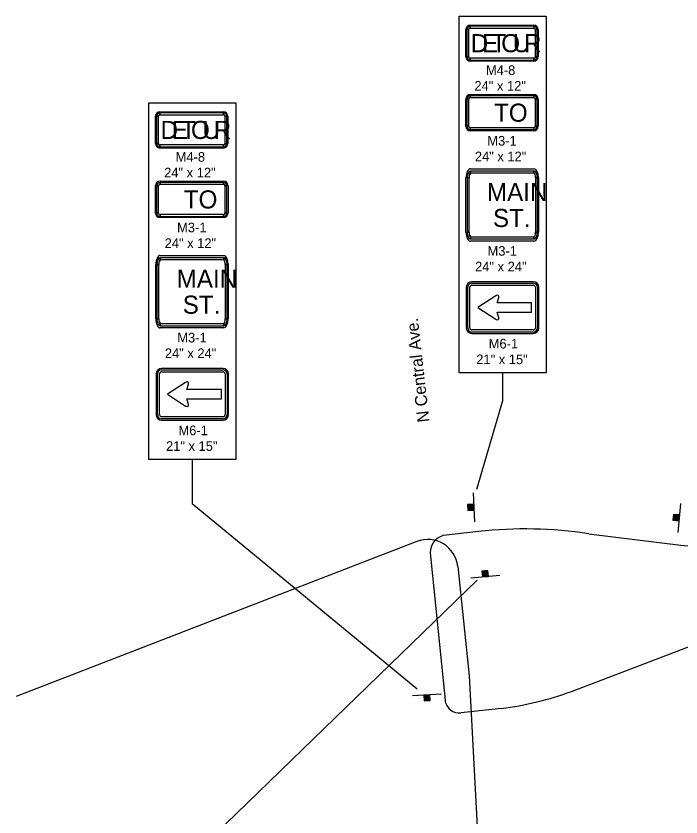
# Model space of a CAD drawing. Extents: x 10133 to 81668, y 6132 to 11018.
# Drawn here: x 10419 to 10970, y 8934 to 9599 of the extents above; entities that cross this region are included whole.
import ezdxf

# ---------------------------------------------------------------- set-up
doc = ezdxf.new("R2010")
doc.units = 0
for name, color, linetype in [('dsnTextFinalPlan', 7, 'Continuous'), ('Level 10', 7, 'Continuous'), ('Level 2', 7, 'Continuous'), ('Level 5', 7, 'Continuous')]:
    doc.layers.add(name, color=color, linetype=linetype)

msp = doc.modelspace()

# ---------------------------------------------------------------- linework, layer by layer
at = {"layer": 'dsnTextFinalPlan'}
for p, q in [((10797.94, 9203.03), (10798.93, 9179.05)), ((10793.69, 9193.37), (10793.89, 9188.49)), ((10794.17, 9188.5), (10793.96, 9193.38)), ((10794.16, 9193.39), (10794.36, 9188.51)), ((10794.64, 9188.52), (10794.44, 9193.4)), ((10794.63, 9193.41), (10794.82, 9188.53)), ((10795.2, 9188.55), (10795.01, 9193.42)), ((10795.19, 9193.43), (10795.39, 9188.56)), ((10795.77, 9188.57), (10795.57, 9193.44)), ((10795.89, 9193.46), (10796.1, 9188.59)), ((10796.37, 9188.6), (10796.19, 9193.47)), ((10796.37, 9193.48), (10796.57, 9188.6)), ((10796.8, 9188.61), (10796.6, 9193.49)), ((10796.89, 9193.5), (10797.09, 9188.63)), ((10797.27, 9188.63), (10797.07, 9193.51)), ((10797.27, 9193.51), (10797.47, 9188.64)), ((10797.7, 9188.65), (10797.5, 9193.52)), ((10797.72, 9193.53), (10797.93, 9188.66)), ((10798.17, 9188.67), (10797.97, 9193.54)), ((10969.88, 9194.1), (10967.69, 9170.2)), ((10964.39, 9185.09), (10963.94, 9180.23)), ((10964.22, 9180.21), (10964.67, 9185.06)), ((10964.86, 9185.05), (10964.42, 9180.19)), ((10964.69, 9180.17), (10965.14, 9185.02)), ((10965.33, 9185), (10964.87, 9180.15)), ((10965.25, 9180.11), (10965.71, 9184.97)), ((10965.89, 9184.95), (10965.44, 9180.1)), ((10965.82, 9180.06), (10966.26, 9184.92)), ((10966.59, 9184.89), (10966.14, 9180.03)), ((10966.42, 9180.01), (10966.88, 9184.86)), ((10967.06, 9184.85), (10966.62, 9179.99)), ((10966.84, 9179.97), (10967.29, 9184.82)), ((10967.58, 9184.8), (10967.14, 9179.94)), ((10967.32, 9179.92), (10967.76, 9184.78)), ((10967.96, 9184.76), (10967.51, 9179.91)), ((10967.74, 9179.89), (10968.19, 9184.74)), ((10968.41, 9184.72), (10967.97, 9179.86)), ((10968.21, 9179.84), (10968.66, 9184.7)), ((10802.29, 9171.01), (10775.92, 9168)), ((10893.98, 9169.13), (10970.3, 9159.56)), ((10751.26, 9162.72), (10418.8, 9034.15)), ((10762.42, 9153.32), (10774.67, 9031.09)), ((10810.12, 9138.18), (10805.26, 9137.77)), ((10805.29, 9137.49), (10810.15, 9137.9)), ((10810.16, 9137.7), (10805.3, 9137.29)), ((10805.33, 9137.02), (10810.19, 9137.43)), ((10810.2, 9137.23), (10805.34, 9136.84)), ((10805.37, 9136.46), (10810.23, 9136.86)), ((10810.25, 9136.68), (10805.39, 9136.27)), ((10805.42, 9135.89), (10810.28, 9136.3)), ((10810.31, 9135.98), (10805.45, 9135.57)), ((10805.47, 9135.29), (10810.33, 9135.68)), ((10810.35, 9135.5), (10805.49, 9135.09)), ((10805.51, 9134.86), (10810.37, 9135.27)), ((10810.39, 9134.98), (10805.53, 9134.57)), ((10805.55, 9134.39), (10810.41, 9134.8)), ((10810.42, 9134.61), (10805.56, 9134.2)), ((10805.58, 9133.97), (10810.44, 9134.38)), ((10819.96, 9134.34), (10796.04, 9132.33)), ((10810.46, 9134.15), (10805.6, 9133.74)), ((10805.62, 9133.5), (10810.48, 9133.9)), ((10879.55, 9038.29), (11002.94, 9085.49)), ((10747.66, 9034.72), (10771.62, 9036.19)), ((10762.01, 9035.24), (10757.14, 9034.94)), ((10757.16, 9034.7), (10762.03, 9034.99)), ((10762.04, 9034.77), (10757.17, 9034.47)), ((10757.19, 9034.24), (10762.06, 9034.54)), ((10762.07, 9034.34), (10757.2, 9034.04)), ((10757.21, 9033.86), (10762.08, 9034.16)), ((10762.1, 9033.87), (10757.23, 9033.57)), ((10757.24, 9033.34), (10762.11, 9033.64)), ((10762.12, 9033.44), (10757.25, 9033.16)), ((10757.27, 9032.87), (10762.14, 9033.17)), ((10762.16, 9032.84), (10757.29, 9032.54)), ((10757.31, 9032.16), (10762.18, 9032.46)), ((10762.19, 9032.27), (10757.33, 9031.99)), ((10757.35, 9031.61), (10762.22, 9031.89)), ((10762.23, 9031.71), (10757.36, 9031.41)), ((10757.38, 9031.14), (10762.25, 9031.43)), ((10762.26, 9031.24), (10757.39, 9030.94)), ((10757.41, 9030.66), (10762.27, 9030.96)), ((10821.28, 9023.98), (10787.9, 9020.36))]:
    msp.add_line(p, q, dxfattribs=at)
for points in [[(10786.31, 9598.82), (10858.38, 9598.82), (10858.38, 9302.72), (10786.31, 9302.72)], [(10786.31, 9598.82), (10858.38, 9598.82), (10858.38, 9302.72), (10786.31, 9302.72)], [(10528.99, 9526.84), (10601.05, 9526.84), (10601.05, 9230.74), (10528.99, 9230.74)], [(10528.99, 9526.84), (10601.05, 9526.84), (10601.05, 9230.74), (10528.99, 9230.74)], [(10798.45, 9188.68), (10798.25, 9193.59), (10793.34, 9193.38), (10793.55, 9188.48)], [(10968.49, 9179.82), (10968.94, 9184.71), (10964.05, 9185.15), (10963.6, 9180.27)], [(10805.65, 9133.22), (10810.54, 9133.63), (10810.13, 9138.52), (10805.23, 9138.11)], [(10761.99, 9035.52), (10757.09, 9035.22), (10757.39, 9030.32), (10762.3, 9030.62)]]:
    msp.add_lwpolyline(points, close=True, dxfattribs=at)
for points in [[(10822.35, 9302.72), (10822.35, 9279.46), (10800.59, 9205.8)], [(10565.02, 9230.74), (10565.02, 9194.13), (10751.41, 9040.3)], [(10785.14, 9142), (10794.64, 9051.15), (10817.78, 8612.5)], [(10556.31, 8842.44), (10556.31, 8892.79), (10801.13, 9130.54)]]:
    msp.add_lwpolyline(points, dxfattribs=at)
for centre, radius, start, end in [((10776.68, 9153.75), 14.27, 93.05001, 181.74125), ((10840.81, 8812.25), 360.82, 81.52677, 96.12941), ((10760.28, 9139.4), 25, 5.96861, 111.14197), ((11056.79, 10017.57), 862.36, 264.24449, 273.255), ((10786, 9293.41), 271.73, 277.46158, 290.13827), ((10786.61, 9032.29), 12, 185.72428, 276.20159)]:
    msp.add_arc(centre, radius, start, end, dxfattribs=at)
at = {"layer": 'Level 10'}
for p, q in [((10791.76, 9565), (10791.76, 9587.55)), ((10792.7, 9587.55), (10794.27, 9587.55)), ((10795.52, 9591.31), (10848.13, 9591.31)), ((10795.52, 9588.8), (10795.52, 9590.37)), ((10848.13, 9590.37), (10848.13, 9588.8)), ((10849.39, 9587.55), (10850.95, 9587.55)), ((10851.89, 9587.55), (10851.89, 9565)), ((10794.27, 9565), (10792.7, 9565)), ((10795.52, 9562.19), (10795.52, 9563.75)), ((10848.13, 9561.25), (10795.52, 9561.25)), ((10848.13, 9563.75), (10848.13, 9562.19)), ((10850.95, 9565), (10849.39, 9565)), ((10795.57, 9533.62), (10848.18, 9533.62)), ((10791.81, 9507.32), (10791.81, 9529.87)), ((10792.75, 9529.87), (10794.31, 9529.87)), ((10795.57, 9531.12), (10795.57, 9532.68)), ((10848.18, 9532.68), (10848.18, 9531.12)), ((10849.43, 9529.87), (10851, 9529.87)), ((10851.94, 9529.87), (10851.94, 9507.32)), ((10534.44, 9493.02), (10534.44, 9515.57)), ((10535.38, 9515.57), (10536.94, 9515.57)), ((10538.2, 9519.33), (10590.81, 9519.33)), ((10538.2, 9516.82), (10538.2, 9518.39)), ((10590.81, 9518.39), (10590.81, 9516.82)), ((10592.06, 9515.57), (10593.63, 9515.57)), ((10594.57, 9515.57), (10594.57, 9493.02)), ((10794.31, 9507.32), (10792.75, 9507.32)), ((10851, 9507.32), (10849.43, 9507.32)), ((10795.57, 9504.5), (10795.57, 9506.06)), ((10848.18, 9503.56), (10795.57, 9503.56)), ((10848.18, 9506.06), (10848.18, 9504.5)), ((10536.94, 9493.02), (10535.38, 9493.02)), ((10538.2, 9490.2), (10538.2, 9491.77)), ((10590.81, 9489.26), (10538.2, 9489.26)), ((10590.81, 9491.77), (10590.81, 9490.2)), ((10593.63, 9493.02), (10592.06, 9493.02)), ((10795.76, 9472.04), (10848.37, 9472.04)), ((10795.76, 9467.03), (10795.76, 9470.16)), ((10848.37, 9470.16), (10848.37, 9468.6)), ((10538.24, 9461.64), (10590.86, 9461.64)), ((10538.24, 9459.14), (10538.24, 9460.7)), ((10590.86, 9460.7), (10590.86, 9459.14)), ((10792, 9419.43), (10792, 9464.52)), ((10792.94, 9464.52), (10794.51, 9464.52)), ((10849.62, 9464.52), (10851.19, 9464.52)), ((10852.13, 9464.52), (10852.13, 9419.43)), ((10534.48, 9435.34), (10534.48, 9457.88)), ((10535.42, 9457.88), (10536.99, 9457.88)), ((10592.11, 9457.88), (10593.67, 9457.88)), ((10594.61, 9457.88), (10594.61, 9435.34)), ((10536.99, 9435.34), (10535.42, 9435.34)), ((10538.24, 9432.52), (10538.24, 9434.08)), ((10590.86, 9434.08), (10590.86, 9432.52)), ((10593.67, 9435.34), (10592.11, 9435.34)), ((10590.86, 9431.58), (10538.24, 9431.58)), ((10794.51, 9419.43), (10792.94, 9419.43)), ((10795.76, 9413.79), (10795.76, 9416.92)), ((10848.37, 9415.36), (10848.37, 9413.79)), ((10851.19, 9419.43), (10849.62, 9419.43)), ((10848.37, 9411.91), (10795.76, 9411.91)), ((10538.43, 9400.06), (10591.05, 9400.06)), ((10538.43, 9395.05), (10538.43, 9398.18)), ((10591.05, 9398.18), (10591.05, 9396.61)), ((10534.68, 9347.45), (10534.68, 9392.54)), ((10535.61, 9392.54), (10537.18, 9392.54)), ((10592.3, 9392.54), (10593.86, 9392.54)), ((10594.8, 9392.54), (10594.8, 9347.45)), ((10792.26, 9373.75), (10792.26, 9339.96)), ((10793.42, 9339.96), (10793.42, 9373.75)), ((10795.14, 9339.96), (10795.14, 9373.75)), ((10847.81, 9378.33), (10796.84, 9378.33)), ((10796.85, 9377.19), (10847.82, 9377.19)), ((10796.85, 9375.47), (10847.82, 9375.47)), ((10849.54, 9373.75), (10849.54, 9339.96)), ((10851.26, 9373.75), (10851.26, 9339.96)), ((10852.39, 9339.96), (10852.39, 9373.75)), ((10537.18, 9347.45), (10535.61, 9347.45)), ((10593.86, 9347.45), (10592.3, 9347.45)), ((10538.43, 9341.81), (10538.43, 9344.94)), ((10591.05, 9343.37), (10591.05, 9341.81)), ((10591.05, 9339.93), (10538.43, 9339.93)), ((10796.84, 9335.38), (10847.81, 9335.38)), ((10847.82, 9338.24), (10796.85, 9338.24)), ((10847.82, 9336.53), (10796.85, 9336.53)), ((10534.94, 9301.77), (10534.94, 9267.98)), ((10536.09, 9267.98), (10536.09, 9301.77)), ((10537.81, 9267.98), (10537.81, 9301.77)), ((10590.48, 9306.35), (10539.52, 9306.35)), ((10539.53, 9305.2), (10590.5, 9305.2)), ((10539.53, 9303.49), (10590.5, 9303.49)), ((10592.21, 9301.77), (10592.21, 9267.98)), ((10593.93, 9301.77), (10593.93, 9267.98)), ((10595.07, 9267.98), (10595.07, 9301.77)), ((10539.52, 9263.4), (10590.48, 9263.4)), ((10590.5, 9266.26), (10539.53, 9266.26)), ((10590.5, 9264.55), (10539.53, 9264.55))]:
    msp.add_line(p, q, dxfattribs=at)
for points in [[(10792.7, 9587.55), (10792.7, 9565), (10794.27, 9565), (10794.27, 9587.55), (10792.7, 9587.55)], [(10848.13, 9590.37), (10795.52, 9590.37), (10795.52, 9588.8), (10848.13, 9588.8), (10848.13, 9590.37)], [(10850.95, 9565), (10850.95, 9587.55), (10849.39, 9587.55), (10849.39, 9565), (10850.95, 9565)], [(10795.52, 9562.19), (10848.13, 9562.19), (10848.13, 9563.75), (10795.52, 9563.75), (10795.52, 9562.19)], [(10792.75, 9529.87), (10792.75, 9507.32), (10794.31, 9507.32), (10794.31, 9529.87), (10792.75, 9529.87)], [(10848.18, 9532.68), (10795.57, 9532.68), (10795.57, 9531.12), (10848.18, 9531.12), (10848.18, 9532.68)], [(10851, 9507.32), (10851, 9529.87), (10849.43, 9529.87), (10849.43, 9507.32), (10851, 9507.32)], [(10535.38, 9515.57), (10535.38, 9493.02), (10536.94, 9493.02), (10536.94, 9515.57), (10535.38, 9515.57)], [(10590.81, 9518.39), (10538.2, 9518.39), (10538.2, 9516.82), (10590.81, 9516.82), (10590.81, 9518.39)], [(10593.63, 9493.02), (10593.63, 9515.57), (10592.06, 9515.57), (10592.06, 9493.02), (10593.63, 9493.02)], [(10795.57, 9504.5), (10848.18, 9504.5), (10848.18, 9506.06), (10795.57, 9506.06), (10795.57, 9504.5)], [(10538.2, 9490.2), (10590.81, 9490.2), (10590.81, 9491.77), (10538.2, 9491.77), (10538.2, 9490.2)], [(10848.37, 9470.16), (10795.76, 9470.16), (10795.76, 9468.6), (10848.37, 9468.6), (10848.37, 9470.16)], [(10590.86, 9460.7), (10538.24, 9460.7), (10538.24, 9459.14), (10590.86, 9459.14), (10590.86, 9460.7)], [(10792.94, 9464.52), (10792.94, 9419.43), (10794.51, 9419.43), (10794.51, 9464.52), (10792.94, 9464.52)], [(10851.19, 9419.43), (10851.19, 9464.52), (10849.62, 9464.52), (10849.62, 9419.43), (10851.19, 9419.43)], [(10535.42, 9457.88), (10535.42, 9435.34), (10536.99, 9435.34), (10536.99, 9457.88), (10535.42, 9457.88)], [(10593.67, 9435.34), (10593.67, 9457.88), (10592.11, 9457.88), (10592.11, 9435.34), (10593.67, 9435.34)], [(10538.24, 9432.52), (10590.86, 9432.52), (10590.86, 9434.08), (10538.24, 9434.08), (10538.24, 9432.52)], [(10795.76, 9413.79), (10848.37, 9413.79), (10848.37, 9415.36), (10795.76, 9415.36), (10795.76, 9413.79)], [(10591.05, 9398.18), (10538.43, 9398.18), (10538.43, 9396.61), (10591.05, 9396.61), (10591.05, 9398.18)], [(10535.61, 9392.54), (10535.61, 9347.45), (10537.18, 9347.45), (10537.18, 9392.54), (10535.61, 9392.54)], [(10593.86, 9347.45), (10593.86, 9392.54), (10592.3, 9392.54), (10592.3, 9347.45), (10593.86, 9347.45)], [(10538.43, 9341.81), (10591.05, 9341.81), (10591.05, 9343.37), (10538.43, 9343.37), (10538.43, 9341.81)]]:
    msp.add_lwpolyline(points, close=True, dxfattribs=at)
for points in [[(10816.8, 9366.67), (10801.82, 9356.86), (10816.81, 9347.07)], [(10819.28, 9348.4), (10817.91, 9352.98), (10846.44, 9352.98), (10846.44, 9360.73), (10817.91, 9360.73), (10819.3, 9365.31)], [(10559.48, 9294.69), (10544.49, 9284.87), (10559.48, 9275.09)], [(10561.95, 9276.42), (10560.58, 9281), (10589.11, 9281), (10589.11, 9288.75), (10560.58, 9288.75), (10561.98, 9293.32)]]:
    msp.add_lwpolyline(points, dxfattribs=at)
for centre, radius, start, end in [((10795.52, 9587.55), 3.76, 90, 180), ((10795.52, 9587.55), 2.82, 90.00021, 179.99985), ((10795.52, 9587.55), 1.25, 90.00021, 179.99985), ((10848.13, 9587.55), 3.76, 0, 90), ((10848.13, 9587.55), 2.82, 0, 90.00021), ((10848.13, 9587.55), 1.25, 0, 90.00021), ((10795.52, 9565), 3.76, 180, 270), ((10795.52, 9565), 2.82, 179.99985, 270.00006), ((10795.52, 9565), 1.25, 179.99985, 270.00006), ((10848.13, 9565), 2.82, 270.00006, 0.00027), ((10848.13, 9565), 1.25, 270.00006, 0.00027), ((10848.13, 9565), 3.76, 270, 359.99112), ((10795.57, 9529.87), 3.76, 90, 180), ((10848.18, 9529.87), 3.76, 0, 90), ((10795.57, 9529.87), 2.82, 90.00021, 179.99985), ((10795.57, 9529.87), 1.25, 90.00021, 179.99985), ((10848.18, 9529.87), 2.82, 0, 90.00021), ((10848.18, 9529.87), 1.25, 0, 90.00021), ((10538.2, 9515.57), 3.76, 90, 180), ((10538.2, 9515.57), 2.82, 90.00021, 179.99985), ((10538.2, 9515.57), 1.25, 90.00021, 179.99985), ((10590.81, 9515.57), 3.76, 0, 90), ((10590.81, 9515.57), 2.82, 0, 90.00021), ((10590.81, 9515.57), 1.25, 0, 90.00021), ((10795.57, 9507.32), 3.76, 180, 270), ((10795.57, 9507.32), 2.82, 179.99985, 270.00006), ((10795.57, 9507.32), 1.25, 179.99985, 270.00006), ((10848.18, 9507.32), 2.82, 270.00006, 0.00027), ((10848.18, 9507.32), 1.25, 270.00006, 0.00027), ((10848.18, 9507.32), 3.76, 270, 359.99112), ((10538.2, 9493.02), 3.76, 180, 270), ((10538.2, 9493.02), 2.82, 179.99985, 270.00006), ((10538.2, 9493.02), 1.25, 179.99985, 270.00006), ((10590.81, 9493.02), 2.82, 270.00006, 0.00027), ((10590.81, 9493.02), 1.25, 270.00006, 0.00027), ((10590.81, 9493.02), 3.76, 270, 359.99112), ((10538.24, 9457.88), 3.76, 90, 180), ((10538.24, 9457.88), 2.82, 90.00021, 179.99985), ((10590.86, 9457.88), 3.76, 0, 90), ((10590.86, 9457.88), 2.82, 0, 90.00021), ((10538.24, 9457.88), 1.25, 90.00021, 179.99985), ((10590.86, 9457.88), 1.25, 0, 90.00021), ((10538.24, 9435.34), 3.76, 180, 270), ((10538.24, 9435.34), 2.82, 179.99985, 270.00006), ((10538.24, 9435.34), 1.25, 179.99985, 270.00006), ((10590.86, 9435.34), 2.82, 270.00006, 0.00027), ((10590.86, 9435.34), 1.25, 270.00006, 0.00027), ((10590.86, 9435.34), 3.76, 270, 359.99112), ((10796.84, 9373.75), 4.58, 90, 180), ((10796.85, 9373.75), 3.44, 90, 180), ((10796.85, 9373.75), 1.72, 90, 180), ((10847.81, 9373.75), 4.58, 360, 90), ((10847.82, 9373.75), 3.44, 0, 90), ((10847.82, 9373.75), 1.72, 0, 90), ((10817.93, 9365.7), 1.43, 344.03092, 123.38906), ((10738.35, 9486.43), 143.16, 303.2286, 303.38906), ((10817.93, 9348.01), 1.4, 236.6896, 15.96908), ((10738.53, 9227.2), 143.16, 56.68961, 56.85697), ((10796.84, 9339.96), 4.58, 180, 270), ((10796.85, 9339.96), 3.44, 180, 270), ((10796.85, 9339.96), 1.72, 180, 270), ((10847.81, 9339.96), 4.58, 270, 0), ((10847.82, 9339.96), 3.44, 270, 0), ((10847.82, 9339.96), 1.72, 270, 0), ((10539.52, 9301.77), 4.58, 90, 180), ((10539.53, 9301.77), 3.44, 90, 180), ((10539.53, 9301.77), 1.72, 90, 180), ((10590.48, 9301.77), 4.58, 360, 90), ((10590.5, 9301.77), 3.44, 0, 90), ((10590.5, 9301.77), 1.72, 0, 90), ((10481.03, 9414.45), 143.16, 303.2286, 303.38906), ((10560.6, 9293.72), 1.43, 344.03092, 123.38906), ((10481.21, 9155.21), 143.16, 56.68961, 56.85697), ((10560.6, 9276.03), 1.4, 236.6896, 15.96908), ((10539.52, 9267.98), 4.58, 180, 270), ((10539.53, 9267.98), 3.44, 180, 270), ((10539.53, 9267.98), 1.72, 180, 270), ((10590.48, 9267.98), 4.58, 270, 0), ((10590.5, 9267.98), 3.44, 270, 0), ((10590.5, 9267.98), 1.72, 270, 0)]:
    msp.add_arc(centre, radius, start, end, dxfattribs=at)
for centre, major_axis, ratio, start_param, end_param in [((10795.76, 9464.52), (0, 7.52), 0.5, 6.283185, 7.853982), ((10795.76, 9464.52), (0, 5.64), 0.5, 0.000004, 1.570794), ((10795.76, 9464.52), (0, 4.07), 0.307692, 0.000004, 1.570794), ((10848.37, 9464.52), (0, 7.52), 0.5, 4.712389, 6.283185), ((10848.37, 9464.52), (0, 5.64), 0.5, 4.712389, 6.283189), ((10848.37, 9464.52), (0, 4.07), 0.307692, 4.712389, 6.283189), ((10795.76, 9419.43), (0, 7.52), 0.5, 1.570796, 3.141593), ((10795.76, 9419.43), (0, 5.64), 0.5, 1.570794, 3.141594), ((10795.76, 9419.43), (0, 4.07), 0.307692, 1.570794, 3.141594), ((10848.37, 9419.43), (0, 5.64), 0.5, 3.141594, 4.712394), ((10848.37, 9419.43), (0, 4.07), 0.307692, 3.141594, 4.712394), ((10848.37, 9419.43), (0, 7.52), 0.5, 3.141593, 4.712234), ((10538.43, 9392.54), (0, 7.52), 0.5, 6.283185, 7.853982), ((10538.43, 9392.54), (0, 5.64), 0.5, 0.000004, 1.570794), ((10538.43, 9392.54), (0, 4.07), 0.307692, 0.000004, 1.570794), ((10591.05, 9392.54), (0, 7.52), 0.5, 4.712389, 6.283185), ((10591.05, 9392.54), (0, 5.64), 0.5, 4.712389, 6.283189), ((10591.05, 9392.54), (0, 4.07), 0.307692, 4.712389, 6.283189), ((10538.43, 9347.45), (0, 7.52), 0.5, 1.570796, 3.141593), ((10538.43, 9347.45), (0, 5.64), 0.5, 1.570794, 3.141594), ((10538.43, 9347.45), (0, 4.07), 0.307692, 1.570794, 3.141594), ((10591.05, 9347.45), (0, 5.64), 0.5, 3.141594, 4.712394), ((10591.05, 9347.45), (0, 4.07), 0.307692, 3.141594, 4.712394), ((10591.05, 9347.45), (0, 7.52), 0.5, 3.141593, 4.712234)]:
    msp.add_ellipse(centre, major_axis=major_axis, ratio=ratio, start_param=start_param, end_param=end_param, dxfattribs=at)

# ---------------------------------------------------------------- texts
for s, height, p in [('D', 15.03, (10796.01, 9568.76)), ('E', 15.03, (10805.24, 9568.76)), ('T', 15.03, (10813.02, 9568.76)), ('O', 15.03, (10821.23, 9568.76)), ('U', 15.03, (10830.82, 9568.76)), ('R', 15.03, (10840.06, 9568.76)), ('TO', 15.032, (10815.23, 9511.08)), ('D', 15.03, (10538.68, 9496.78)), ('E', 15.03, (10547.92, 9496.78)), ('T', 15.03, (10555.7, 9496.78)), ('O', 15.03, (10563.91, 9496.78)), ('U', 15.03, (10573.5, 9496.78)), ('R', 15.03, (10582.74, 9496.78)), ('MAIN', 15.032, (10809.33, 9445.23)), ('TO', 15.032, (10557.91, 9439.09)), ('ST.', 15.032, (10814.38, 9423.69)), ('MAIN', 15.032, (10552, 9373.24)), ('ST.', 15.032, (10557.05, 9351.71))]:
    msp.add_text(s, height=height, dxfattribs=at).set_placement(p)
at = {"layer": 'Level 2'}
msp.add_text('N Central Ave.', height=10, rotation=96.4177, dxfattribs=at).set_placement((10761.77, 9262.14))
at = {"layer": 'Level 5'}
for s, p in [('M4-8', (10808.53, 9549.86)), ('24" x 12"', (10798.98, 9536.86)), ('M3-1', (10809.69, 9491.27)), ('M4-8', (10551.2, 9477.88)), ('24" x 12"', (10799.36, 9478.27)), ('24" x 12"', (10541.65, 9464.88)), ('M3-1', (10552.37, 9419.29)), ('24" x 12"', (10542.04, 9406.29)), ('M3-1', (10809.88, 9399.87)), ('24" x 24"', (10799.55, 9386.87)), ('M3-1', (10552.56, 9327.89)), ('M6-1', (10810.85, 9322.87)), ('24" x 24"', (10542.23, 9314.89)), ('21" x 15"', (10800.52, 9309.87)), ('M6-1', (10553.53, 9250.89)), ('21" x 15"', (10543.2, 9237.89))]:
    msp.add_text(s, height=8, dxfattribs=at).set_placement(p)

doc.saveas('drawing.dxf')
